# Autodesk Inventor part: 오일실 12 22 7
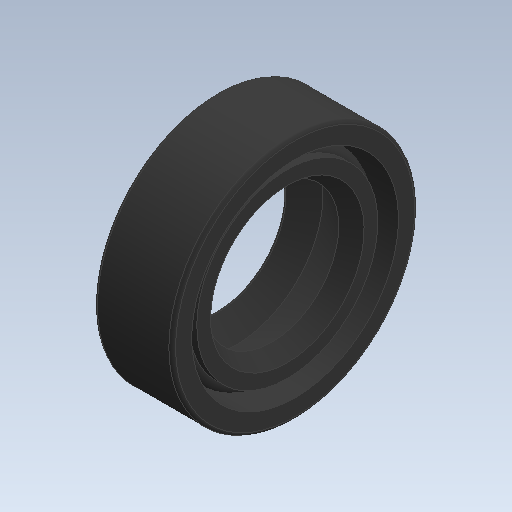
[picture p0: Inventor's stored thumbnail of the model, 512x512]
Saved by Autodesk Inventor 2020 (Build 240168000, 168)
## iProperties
Created: 2024-05
Part Number: 오일실 12 22 7
Material: 고무
Description: 오일-실
Document SubType Name: Modeling
Designer: oem
Density: 0.93 g/cm^3
Appearance: 기본값
Author: jhkim
Sending System: Autodesk Inventor 2025
Preprocessor: ST-DEVELOPER v20
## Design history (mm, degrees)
feature "Solid1"
node "솔리드1"
